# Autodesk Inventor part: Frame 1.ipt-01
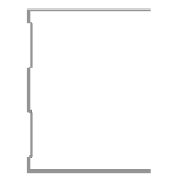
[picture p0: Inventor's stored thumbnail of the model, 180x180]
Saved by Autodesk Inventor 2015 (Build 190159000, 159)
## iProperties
Created: 2015-04
Part Number: Frame 1.ipt-01
Material: Aluminum 6061
Document SubType Name: Modeling
Standard: Unnamed
Designer: suporte
Language: en-US
Size Designation: (Unnamed 1)
Categories: <MemberInstance><Categories><Category DisplayName="Structural Shapes" InternalName="089c4875-fa83-4c05-b084-43b9cc11f5ed" Mnemonic="GRDR"><CategoryParameter Dis
Density: 2.7 g/cm^3
Appearance: Aluminum - Flat
_CCFamilyMember: 1
_CCFamilyDisplayName: Frame 1
_FrameMemberDoc: Frame Member File
_Version: 15.0.0
_GetPNFromCC: 1
IsCustomPart: 1
Author: suporte
G_L: 2100,000 mm
G_W: 70,000 mm
G_H: 75,000 mm
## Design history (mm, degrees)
node "Start Plane"
node "End Plane"
sketch "Sketch"
  geometry: L1 (34.6, 37.5)-(34.6, 36.7); L2 (34.6, 36.7)-(-34.6, 36.7); L3 (-34.6, -36.7)-(34.6, -36.7); L4 (34.6, -36.7)-(34.6, -37.5); L5 (34.6, -37.5)-(-35.4, -37.5); L6 (-35.4, 37.5)-(34.6, 37.5); L7 (-34.6, 36.7)-(-34.6, 31.7); L8 (-34.6, 31.7)-(-33.4, 30.5); L9 (-33.4, 30.5)-(-33.4, 10.746); L10 (-33.4, 10.746)-(-34.6, 9.546); L11 (-34.6, 9.546)-(-34.6, -9.546); L12 (-34.6, -9.546)-(-33.4, -10.746); L13 (-33.4, -10.746)-(-33.4, -30.5); L14 (-33.4, -30.5)-(-34.6, -31.7); L15 (-34.6, -31.7)-(-34.6, -36.7); L16 (-35.4, -37.5)-(-35.4, -31.369); L17 (-35.4, -31.369)-(-34.2, -30.169); L18 (-34.2, -30.169)-(-34.2, -11.077); L19 (-34.2, -11.077)-(-35.4, -9.877); L20 (-35.4, -9.877)-(-35.4, 9.877); L21 (-35.4, 9.877)-(-34.2, 11.077); L22 (-34.2, 11.077)-(-34.2, 30.169); L23 (-34.2, 30.169)-(-35.4, 31.369); L24 (-35.4, 31.369)-(-35.4, 37.5); L25 (-35.4, 0)-(30.37, 0); 3 further points
  constraints: 50 end point, 10 point on line, 9 parallel, 5 perpendicular, 4 equal length, 3 midpoint, 3 vertical, 2 vertical alignment, 1 collinear, 1 horizontal, 1 horizontal alignment
  dimensions: "d3" = 0.8 distance of L1.start L1.end; "d5" = 75 distance between parallel lines of L5 L6; "d6" = 0.8 distance between parallel lines of L24 L7; "d7" = 0.8 distance between parallel lines of L8 L23; "d8" = 0.8 distance between parallel lines of L22 L9; "d9" = 0.8 distance between parallel lines of L17 L14; "d10" = 0.8 distance between parallel lines of L13 L18; "d11" = 0.8 distance between parallel lines of L12 L19; "d12" = 0.8 distance between parallel lines of L21 L10; "d13" = 5 distance of L2.end L7.end; "d15" = 135 deg angle of L9 L8; "d16" = 2 distance between parallel lines of L24 L9; "d17" = 70 distance of L6.start L1.start
extrude "Body" join sketch "Sketch" stored distance "d24" = 0.13; taper "d25" = 0 deg
node "Driven Length"
  sketch "Sketch8"
    geometry: L1 (0, 0)-(10, 0) reference
    constraints: 2 end point, 1 horizontal
  workplane "Work Plane6"
  sketch "Sketch9"
    geometry: L1 (-2, 0)-(12, 0) reference; L2 (-2, 2100)-(12, 2100) reference
    dimensions: "d27" = 2100 distance between parallel lines of L1 L2 (derived)
body "Solid1"
other parameters: "G_OFFSET_START" = 0 [user parameter; used in 1 equation term], "G_OFFSET_END" = 0 [user parameter; used in 1 equation term], "d22" = 0 (computed from G_OFFSET_START), "G_L" = 2100 (= d27) [user parameter], "d32" = 90 deg
